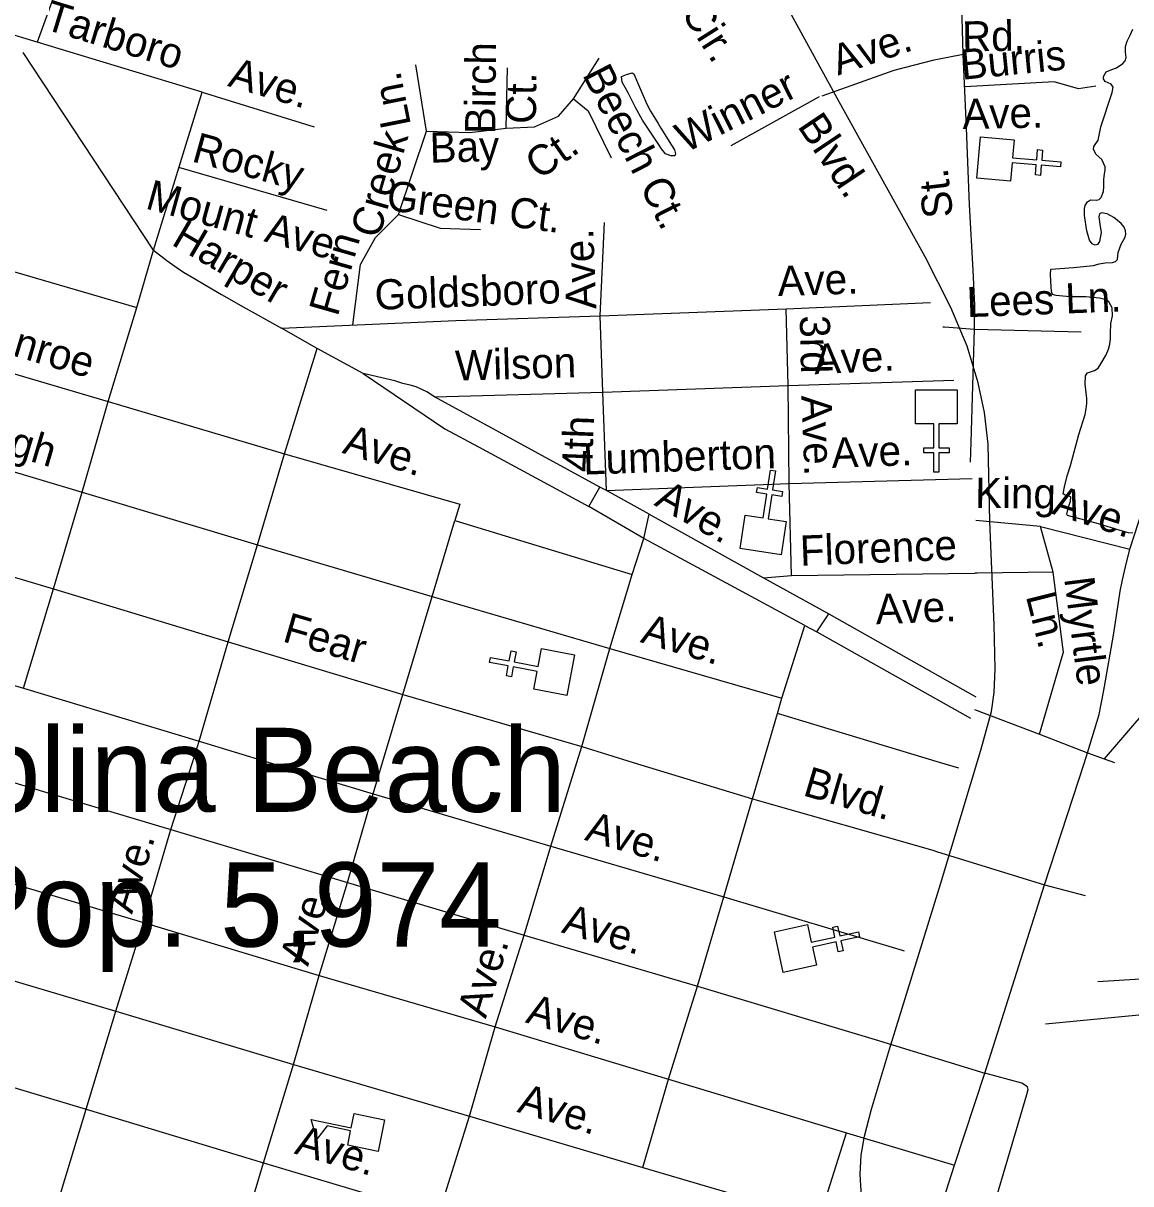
# Model space of a CAD drawing. Extents: x 2290055 to 2389491, y 66597 to 237875.
# Drawn here: x 2332155 to 2335643, y 104033 to 107689 of the extents above; entities that cross this region are included whole.
import ezdxf

# ---------------------------------------------------------------- set-up
doc = ezdxf.new("R2010")
doc.units = 0
for name, color, linetype in [('Exist Civil Demographics City Label', 7, 'Continuous'), ('Exist Cultural Church CELL', 7, 'Continuous'), ('Exist Cultural Educational Facility High CELL', 7, 'Continuous'), ('Exist Hydrographic Island Shore', 7, 'Continuous'), ('Exist Hydrographic Pond Under 1500 Sq Ft', 7, 'Continuous'), ('Exist Road Non-System Type 51', 7, 'Continuous'), ('Exist Road Non-System Type 51 Label', 7, 'Continuous'), ('Exist Road Primary US Attributed', 7, 'Continuous'), ('Exist Road Primary US Label', 7, 'Continuous')]:
    doc.layers.add(name, color=color, linetype=linetype)

msp = doc.modelspace()

# ---------------------------------------------------------------- linework, layer by layer
at = {"layer": 'Exist Cultural Church CELL'}
for points in [[(2335275.8, 107322.1), (2335271.2, 107265.4), (2335347.1, 107259.1), (2335349.7, 107291), (2335365.7, 107289.6), (2335363, 107257.7), (2335422.9, 107252.8), (2335421.6, 107236.8), (2335361.7, 107241.8), (2335359, 107209.9), (2335343.1, 107211.2), (2335345.7, 107243.1), (2335269.9, 107249.4), (2335265, 107192), (2335158.9, 107200.8), (2335169.7, 107331)], [(2335096.2, 106427.6), (2335039.3, 106427.5), (2335039.3, 106351.3), (2335071.3, 106351.3), (2335071.3, 106335.4), (2335039.3, 106335.4), (2335039.3, 106275.2), (2335023.2, 106275.2), (2335023.2, 106335.4), (2334991.2, 106335.4), (2334991.2, 106351.3), (2335023.2, 106351.3), (2335023.2, 106427.5), (2334965.6, 106427.6), (2334965.6, 106534), (2335096.2, 106534)], [(2334429, 106139.2), (2334485.3, 106130.6), (2334496.8, 106205.9), (2334465.2, 106210.8), (2334467.7, 106226.6), (2334499.3, 106221.7), (2334508.4, 106281.1), (2334524.3, 106278.7), (2334515.1, 106219.2), (2334546.7, 106214.4), (2334544.3, 106198.6), (2334512.7, 106203.5), (2334501.1, 106128.2), (2334558.1, 106119.3), (2334541.9, 106014.1), (2334412.8, 106034)], [(2333763, 105591.2), (2333773.6, 105647.1), (2333698.8, 105661.4), (2333692.8, 105629.9), (2333677.1, 105632.9), (2333683.1, 105664.4), (2333624, 105675.6), (2333627, 105691.3), (2333686.1, 105680.1), (2333692.1, 105711.5), (2333707.7, 105708.6), (2333701.8, 105677.1), (2333776.6, 105662.9), (2333787.5, 105719.5), (2333892, 105699.6), (2333867.6, 105571.3)], [(2334624.8, 104849.4), (2334637.3, 104793.8), (2334711.6, 104810.3), (2334704.7, 104841.6), (2334720.3, 104845), (2334727.2, 104813.8), (2334785.9, 104826.8), (2334789.4, 104811.2), (2334730.7, 104798.2), (2334737.6, 104766.9), (2334722, 104763.5), (2334715.1, 104794.7), (2334640.8, 104778.2), (2334653.2, 104721.9), (2334549.2, 104698.8), (2334520.9, 104826.3)]]:
    msp.add_lwpolyline(points, close=True, dxfattribs=at)
at = {"layer": 'Exist Cultural Educational Facility High CELL'}
msp.add_lwpolyline([(2333273.1, 104135), (2333177.2, 104154.9), (2333186.5, 104199.9), (2333113, 104215.1), (2333079.7, 104174), (2333062.6, 104235.4), (2333188.5, 104209.3), (2333197.8, 104254.4), (2333293.7, 104234.6)], close=True, dxfattribs=at)
at = {"layer": 'Exist Hydrographic Island Shore'}
for points in [[(2335497.5, 107083.2), (2335497.2, 107105.3), (2335499.5, 107114.9), (2335507.2, 107126.2), (2335516.2, 107132.6), (2335536.2, 107131.9), (2335543.7, 107133.9), (2335550.5, 107140), (2335558, 107158.8), (2335558.7, 107175), (2335558.5, 107196.4), (2335560.5, 107214.7), (2335563.2, 107225.9), (2335562.7, 107236.9), (2335552, 107259.7), (2335534, 107275.5), (2335526.2, 107291.5), (2335527.5, 107300.4), (2335540.5, 107320.3), (2335549.2, 107362.8), (2335585.2, 107470.6), (2335587.5, 107487.6), (2335582, 107496.7), (2335562.5, 107505.5), (2335557.7, 107514.1), (2335557.2, 107521.6), (2335565.7, 107535.8), (2335583.7, 107543.9), (2335598, 107548.8), (2335618.5, 107562.3), (2335626.2, 107571.1), (2335629.2, 107580.8), (2335627.2, 107598), (2335627, 107615.8), (2335632, 107632.8), (2335641.5, 107651.2), (2335650.2, 107670.5)], [(2335504.7, 106507.3), (2335500.2, 106552.2), (2335500.5, 106578.1), (2335507.5, 106588), (2335529, 106594.8), (2335540.7, 106602.7), (2335549, 106615.8), (2335565.5, 106645), (2335573, 106662.8), (2335577.7, 106678.2), (2335580, 106695.5), (2335579.5, 106711.9), (2335580.5, 106743.2), (2335585.7, 106767.8), (2335584.7, 106792.1), (2335574.5, 106811.4), (2335565.5, 106818.2), (2335544.5, 106823.1), (2335501.5, 106827.1), (2335453, 106827.6), (2335429, 106829.1), (2335408.5, 106831.1), (2335396.5, 106834.6), (2335393.5, 106843.6), (2335391.2, 106875.9), (2335390.5, 106899.1), (2335392, 106914.8), (2335463.2, 106919.2), (2335526, 106926), (2335544, 106931.6), (2335563.2, 106933.9), (2335586, 106935.4), (2335595.5, 106938.3), (2335601.5, 106944.9), (2335604.2, 106966.8), (2335613.5, 106993), (2335625.7, 107015.6), (2335628.2, 107024.6), (2335627, 107035.6), (2335622.2, 107046.3), (2335612.7, 107058.2), (2335590, 107076.7), (2335568.7, 107088.7), (2335550.7, 107091.4), (2335544.7, 107088.7), (2335542.7, 107079.7), (2335545.5, 107055.8), (2335549.7, 107030), (2335544.7, 107001.9), (2335538.7, 106992.5), (2335531, 106989.8), (2335521.5, 106994.3), (2335513, 107005.4), (2335504.5, 107035.5), (2335497.5, 107083.2)], [(2335650, 106082.3), (2335636.5, 106083.9), (2335610.2, 106090.9), (2335542, 106112.5), (2335443.7, 106138.1), (2335442.5, 106142.1), (2335447.5, 106164.6), (2335453.2, 106183.3), (2335454.2, 106196.8), (2335435.2, 106203.6), (2335430.5, 106206.9), (2335434.2, 106228.5), (2335443, 106263.4), (2335453.2, 106296.2), (2335479.7, 106393.8), (2335499.5, 106456.8), (2335503.2, 106474.4), (2335505.5, 106491.3), (2335504.7, 106507.3)]]:
    msp.add_lwpolyline(points, dxfattribs=at)
at = {"layer": 'Exist Hydrographic Pond Under 1500 Sq Ft'}
msp.add_lwpolyline([(2334207.2, 107271.5), (2334194.5, 107271.6), (2334178.2, 107277.9), (2334166, 107293.8), (2334155.7, 107307.9), (2334105.5, 107383.7), (2334084, 107424.2), (2334060.5, 107469.4), (2334041.2, 107504), (2334039.7, 107521), (2334055.5, 107527.9), (2334072.7, 107532.9), (2334078, 107530.1), (2334089.5, 107502.5), (2334102.5, 107473.2), (2334115.7, 107441.6), (2334123.2, 107425.7), (2334131, 107411.8), (2334146.2, 107386.9), (2334155.5, 107373.1), (2334163, 107359), (2334181, 107330.7), (2334194.7, 107308.1), (2334206, 107290.6), (2334210, 107277.5), (2334207.2, 107271.5)], dxfattribs=at)
at = {"layer": 'Exist Road Non-System Type 51'}
for p, q in [((2332718.5, 107472.4), (2332130.5, 107650.4)), ((2332565.8, 106974.7), (2332155, 107596.6)), ((2332565.8, 106974.7), (2332718.5, 107472.4)), ((2332718.5, 107472.4), (2333071.7, 107362.3)), ((2334662, 107457.6), (2334384.4, 107302.9)), ((2331961.7, 106954.5), (2332513.5, 106794.1)), ((2332513.5, 106794.1), (2332565.8, 106974.7)), ((2334558.2, 106789.1), (2335012.5, 106809.3)), ((2332422.8, 106497.1), (2332513.5, 106794.1)), ((2333972.2, 106767.3), (2334558.2, 106789.1)), ((2333980.7, 106527.4), (2333972.2, 106767.3)), ((2334564.8, 106547.5), (2334558.2, 106789.1)), ((2333081.2, 106664.2), (2332968.4, 106728.7)), ((2335051.4, 106732.7), (2335057, 106732.3)), ((2335057, 106732.3), (2335150.8, 106725.2)), ((2335140.8, 106369), (2335150.8, 106725.2)), ((2331874.9, 106659.6), (2332422.8, 106497.1)), ((2332978.4, 106332.9), (2333081.2, 106664.2)), ((2333225.8, 106585.6), (2333081.2, 106664.2)), ((2333980.7, 106527.4), (2334564.8, 106547.5)), ((2334564.8, 106547.5), (2335086, 106564.3)), ((2334568.1, 106239.1), (2334564.8, 106547.5)), ((2333450.6, 106511.7), (2333980.7, 106527.4)), ((2333971.8, 106227.1), (2333450.6, 106511.7)), ((2333991.9, 106217.3), (2333980.7, 106527.4)), ((2332341.5, 106212.3), (2332422.8, 106497.1)), ((2332422.8, 106497.1), (2332978.4, 106332.9)), ((2331789.9, 106376.6), (2332341.5, 106212.3)), ((2335139.1, 106306.3), (2335140.8, 106369)), ((2332893.6, 106045.7), (2332978.4, 106332.9)), ((2334568.1, 106239.1), (2335143.6, 106255)), ((2333936.5, 106166.6), (2333971.8, 106227.1)), ((2333991.9, 106217.3), (2333971.8, 106227.1)), ((2333991.9, 106217.3), (2334568.1, 106239.1)), ((2334126.8, 106142.6), (2333991.9, 106217.3)), ((2334574.9, 105949.2), (2334568.1, 106239.1)), ((2332250.8, 105907.1), (2332341.5, 106212.3)), ((2332341.5, 106212.3), (2332893.6, 106045.7)), ((2335640.6, 106032.3), (2335696.8, 106206.8)), ((2334109.8, 106066.4), (2333936.5, 106166.6)), ((2334109.8, 106066.4), (2334126.8, 106142.6)), ((2334126.8, 106142.6), (2334486.9, 105942.1)), ((2333443.2, 105883.6), (2333514.8, 106122.4)), ((2333514.8, 106122.4), (2334073, 105952.1)), ((2335359.5, 106103.2), (2335155.2, 106123.1)), ((2331700.8, 106071.5), (2332250.8, 105907.1)), ((2335359.5, 106103.2), (2335640.6, 106032.3)), ((2335399, 105959.7), (2335359.5, 106103.2)), ((2332800.6, 105740.7), (2332893.6, 106045.7)), ((2332893.6, 106045.7), (2333443.2, 105883.6)), ((2334073, 105952.1), (2334109.8, 106066.4)), ((2334616.6, 105791.7), (2334109.8, 106066.4)), ((2335399, 105959.7), (2335159.2, 105957.1)), ((2334003, 105719.2), (2334073, 105952.1)), ((2334486.9, 105942.1), (2334574.9, 105949.2)), ((2334486.9, 105942.1), (2334692.3, 105828.5)), ((2334574.9, 105949.2), (2335152.6, 105957.1)), ((2335159.2, 105957.1), (2335152.6, 105957.1)), ((2332155.9, 105594.2), (2332250.8, 105907.1)), ((2332250.8, 105907.1), (2332800.6, 105740.7)), ((2333350.7, 105574.3), (2333443.2, 105883.6)), ((2333443.2, 105883.6), (2334003, 105719.2)), ((2334655.1, 105771.9), (2334692.3, 105828.5)), ((2334692.3, 105828.5), (2335155.2, 105567.1)), ((2334544.9, 105562.7), (2334616.6, 105791.7)), ((2334616.6, 105791.7), (2334655.1, 105771.9)), ((2331608.1, 105758.6), (2332155.9, 105594.2)), ((2332709.9, 105427.6), (2332800.6, 105740.7)), ((2332800.6, 105740.7), (2333350.7, 105574.3)), ((2334655.1, 105771.9), (2335139, 105499.7)), ((2333914.5, 105410.2), (2334003, 105719.2)), ((2334003, 105719.2), (2334544.9, 105562.7)), ((2332155.9, 105594.2), (2332709.9, 105427.6)), ((2333287.2, 105360.7), (2333350.7, 105574.3)), ((2333350.7, 105574.3), (2333914.5, 105410.2)), ((2334531.3, 105514.6), (2334544.9, 105562.7)), ((2335151.5, 105526.9), (2335356.4, 105449)), ((2334486.2, 105360.7), (2334531.3, 105514.6)), ((2335040.7, 105360.7), (2334531.3, 105514.6)), ((2335356.4, 105449), (2335507.1, 105390.6)), ((2332688.5, 105360.7), (2332709.9, 105427.6)), ((2332709.9, 105427.6), (2332930.4, 105360.7)), ((2333899.2, 105360.7), (2333914.5, 105410.2)), ((2333914.5, 105410.2), (2334076, 105360.7)), ((2335497.4, 105360.7), (2335507.1, 105390.6)), ((2335507.1, 105390.6), (2335559.4, 105371.3)), ((2332620.8, 105149.1), (2332688.5, 105360.7)), ((2332930.4, 105360.7), (2333257.7, 105261.5)), ((2333257.7, 105261.5), (2333287.2, 105360.7)), ((2333817.5, 105097.1), (2333899.2, 105360.7)), ((2334076, 105360.7), (2334452.3, 105245.6)), ((2334452.3, 105245.6), (2334486.2, 105360.7)), ((2335101.4, 105342.4), (2335040.7, 105360.7)), ((2335371.5, 104975), (2335497.4, 105360.7)), ((2335559.4, 105371.3), (2335591.8, 105360.7)), ((2333176.8, 104982.6), (2333257.7, 105261.5)), ((2333257.7, 105261.5), (2333817.5, 105097.1)), ((2334361.5, 104936.8), (2334452.3, 105245.6)), ((2334452.3, 105245.6), (2335020.3, 105083.6)), ((2332533.9, 104855.8), (2332620.8, 105149.1)), ((2332620.8, 105149.1), (2333176.8, 104982.6)), ((2333732.8, 104816.1), (2333817.5, 105097.1)), ((2333817.5, 105097.1), (2334361.5, 104936.8)), ((2335020.3, 105083.6), (2335031.6, 105080.3)), ((2335031.6, 105080.3), (2335371.5, 104975)), ((2333087.9, 104689.6), (2333176.8, 104982.6)), ((2333176.8, 104982.6), (2333732.8, 104816.1)), ((2335183.6, 104381), (2335371.5, 104975)), ((2335371.5, 104975), (2335499.9, 104940.7)), ((2334278.4, 104655.8), (2334361.5, 104936.8)), ((2334361.5, 104936.8), (2334923.4, 104768.6)), ((2332446.7, 104576.7), (2332533.9, 104855.8)), ((2332533.9, 104855.8), (2333087.9, 104689.6)), ((2333641.8, 104527), (2333732.8, 104816.1)), ((2333732.8, 104816.1), (2334278.4, 104655.8)), ((2334923.4, 104768.6), (2334929.4, 104766.8)), ((2333006.7, 104408.7), (2333087.9, 104689.6)), ((2333087.9, 104689.6), (2333641.8, 104527)), ((2334187.5, 104362.8), (2334278.4, 104655.8)), ((2334278.4, 104655.8), (2334838.4, 104487.6)), ((2332353.9, 104267.8), (2332446.7, 104576.7)), ((2332446.7, 104576.7), (2333006.7, 104408.7)), ((2333560.6, 104246.1), (2333641.8, 104527)), ((2333641.8, 104527), (2334187.5, 104362.8)), ((2334838.4, 104487.6), (2335183.6, 104381)), ((2332912, 104099.4), (2333006.7, 104408.7)), ((2333006.7, 104408.7), (2333560.6, 104246.1)), ((2334106.3, 104083.8), (2334187.5, 104362.8)), ((2334187.5, 104362.8), (2334748.2, 104193.5)), ((2335088.6, 104092.1), (2335183.6, 104381)), ((2332265, 103976.7), (2332353.9, 104267.8)), ((2332353.9, 104267.8), (2332912, 104099.4)), ((2333463.6, 103935.1), (2333560.6, 104246.1)), ((2333560.6, 104246.1), (2334106.3, 104083.8)), ((2334662.1, 103921.6), (2334748.2, 104193.5)), ((2334748.2, 104193.5), (2335088.6, 104092.1)), ((2332825, 103806.5), (2332912, 104099.4)), ((2332912, 104099.4), (2333463.6, 103935.1)), ((2334106.3, 104083.8), (2334662.1, 103921.6)), ((2335001.5, 103821.1), (2335088.6, 104092.1))]:
    msp.add_line(p, q, dxfattribs=at)
for points in [[(2332325.8, 108021.8), (2332300.3, 107907.3), (2332199.1, 107629.7)], [(2335116, 107591.3), (2335109.6, 107821.5)], [(2333676.1, 107358.1), (2333765.2, 107362.3), (2333841.5, 107396.3), (2333888.2, 107451.5), (2333968.8, 107578.8)], [(2334671.2, 107460.8), (2334898.4, 107541), (2335024.1, 107574.2), (2335116, 107591.3)], [(2335150.8, 106725.2), (2335152.2, 106799.4), (2335147.1, 106911.5), (2335135, 107117.1), (2335126.5, 107359.3), (2335116, 107591.3)], [(2333193.6, 106738.5), (2333218.1, 106929.4), (2333264.7, 107014.3), (2333336.8, 107086.5), (2333425.9, 107349.6), (2333392, 107557.6)], [(2333425.9, 107349.6), (2333561.6, 107345.4), (2333676.1, 107358.1), (2333680.4, 107549.1)], [(2335533.7, 107491.3), (2335478.6, 107482.9), (2335402.2, 107504.1), (2335120.6, 107489)], [(2333888.2, 107451.5), (2333934.8, 107413.3), (2334006.9, 107264.7)], [(2333112.1, 107099.2), (2332645.5, 107234.5)], [(2333336.8, 107086.5), (2333468.3, 107044), (2333595.5, 107039.8)], [(2333972.2, 106767.3), (2333985.7, 107061)], [(2332565.8, 106974.7), (2332608.2, 106941.3), (2332639.9, 106918.2), (2332660.1, 106904.9), (2332692.7, 106886.2), (2332732, 106863.4), (2332779.4, 106834.8), (2332847.6, 106795.8), (2332968.4, 106728.7)], [(2332968.4, 106728.7), (2333518.2, 106752.7), (2333972.2, 106767.3)], [(2335150.8, 106725.2), (2335487, 106717.2)], [(2333450.6, 106511.7), (2333426.6, 106527.5), (2333410.6, 106535.4), (2333392.5, 106543.2), (2333374.3, 106549.1), (2333350.4, 106554.7), (2333326.1, 106562.6), (2333225.8, 106585.6)], [(2333225.8, 106585.6), (2333483.7, 106411.9), (2333588.7, 106355), (2333936.5, 106166.6)], [(2332978.4, 106332.9), (2333530.5, 106174.5), (2333514.8, 106122.4)], [(2335979.5, 106127.7), (2335899.6, 105907), (2335827.9, 105712.1), (2335818.2, 105684.2), (2335806.1, 105665.6), (2335792.5, 105643.4), (2335693.7, 105528.6), (2335559.4, 105371.3)], [(2335507.1, 105390.6), (2335543.7, 105511.2), (2335549.5, 105539), (2335553.3, 105559.2), (2335560.9, 105599.2), (2335589.3, 105761.5), (2335604.3, 105863.8), (2335609.8, 105899.8), (2335616.9, 105935.5), (2335626.4, 105976.9), (2335640.6, 106032.3)], [(2335356.4, 105449), (2335427.8, 105694), (2335431.9, 105708), (2335429.6, 105724), (2335399, 105959.7)], [(2331916.6, 105360.7), (2332219.6, 105268.8), (2332620.8, 105149.1)], [(2331438.1, 105184.8), (2332108.4, 104983.4), (2332533.9, 104855.8)], [(2331350.9, 104899.7), (2331977.2, 104716), (2332446.7, 104576.7)], [(2331262.2, 104594.6), (2331816.2, 104428.4), (2332353.9, 104267.8)], [(2335155.8, 103770.4), (2335316.2, 104314.4), (2335320.2, 104330.3), (2335317.9, 104338.4), (2335300, 104350.2), (2335183.6, 104381)]]:
    msp.add_lwpolyline(points, dxfattribs=at)
at = {"layer": 'Exist Road Non-System Type 51 Label'}
for points in [[(2336060.9, 104701.8), (2335539.4, 104668.8)], [(2336060.9, 104602.2), (2335374.7, 104536.3)]]:
    msp.add_lwpolyline(points, dxfattribs=at)
at = {"layer": 'Exist Road Primary US Attributed'}
msp.add_lwpolyline([(2334795.8, 103992.6), (2334791.2, 104063.3), (2334794.3, 104123.3), (2334805.1, 104183.2), (2334826.6, 104267.8), (2334883.4, 104456.8), (2335044.7, 104976.4), (2335170.7, 105399), (2335204.5, 105520.5), (2335213.7, 105580.4), (2335216.8, 105655.7), (2335213.7, 105794.1), (2335199.9, 106119.9), (2335193.8, 106362.8), (2335183, 106462.7), (2335163, 106556.4), (2335127.7, 106671.7), (2335077, 106793.1), (2334995.6, 106953), (2334725.2, 107441.8), (2334479.4, 107890.6)], dxfattribs=at)

# ---------------------------------------------------------------- texts
at = {"layer": 'Exist Civil Demographics City Label'}
for s, p in [('Carolina Beach', (2331441.6, 105204.7)), ('Pop. 5,974', (2331948.2, 104780.3))]:
    msp.add_text(s, height=265, dxfattribs=at).set_placement(p)
at = {"layer": 'Exist Road Non-System Type 51 Label'}
for s, rotation, p in [('Colonial Cir.', 302.2561, (2333960.5, 108142.6)), ('Tarboro', 342.9494, (2332216.9, 107672.1)), ('Rd.', 0.841, (2335112.7, 107600.1)), ('Ave.', 18.6992, (2334721.2, 107524.1)), ('Birch ', 89.414, (2333641.7, 107339.5)), ('Burris', 5.7107, (2335112.1, 107510.8)), ('Ave.', 343.4764, (2332796.8, 107492.1)), ('Beech Ct.', 297.117, (2333915, 107527.7)), ('Ln.', 101.2821, (2333376.8, 107368.9)), ('Ct.', 89.414, (2333770.1, 107371.6)), ('Winner', 26.9131, (2334241.4, 107279.7)), ('Ave.', 1.0532, (2335114, 107355.9)), ('Creek', 74.0171, (2333275.8, 107007.8)), ('Rocky', 344.5112, (2332682.7, 107254.8)), ('Bay ', 1.433, (2333436.6, 107249.7)), ('Ct.', 34.7799, (2333779.7, 107193.7)), ('St.', 96.6193, (2335084.4, 107081)), ('Mount Ave.', 344.5112, (2332536.8, 107106.3)), ('Green Ct.', 352.4052, (2333296.2, 107101.1)), ('Harper', 329.7459, (2332618.7, 106993.2)), ('Fern', 73.9575, (2333145.3, 106762.5)), ('Ave.', 92.2519, (2333960.5, 106789.6)), ('Ave.', 1.8708, (2334532.6, 106829.4)), ('Goldsboro', 2.0826, (2333263.9, 106786)), ('Lees Ln.', 2.1591, (2335128.3, 106763)), ('Monroe', 343.4773, (2331949.6, 106693.1)), ('3rd', 271.4011, (2334600.7, 106768)), ('Wilson', 1.6924, (2333516.9, 106562.9)), ('Ave.', 2.6716, (2334647.5, 106583.3)), ('Ave.', 272.2952, (2334605.8, 106515.8)), ('Raleigh', 343.4292, (2331829.2, 106412.8)), ('4th', 87.8875, (2333946.7, 106274)), ('Ave.', 342.8902, (2333157.2, 106336.1)), ('Lumberton', 1.9544, (2333920.2, 106267)), ('Ave.', 1.9989, (2334702.4, 106288.2)), ('King', 359.4918, (2335152.9, 106162.5)), ('Ave.', 330.5498, (2334139.6, 106172.2)), ('Ave.', 342.1793, (2335391.9, 106144.7)), ('Florence', 2.2118, (2334603.3, 105980)), ('Myrtle', 277.1962, (2335433.6, 105939.9)), ('Ave.', 2.2118, (2334841.3, 105795.7)), ('Ln.', 284.1571, (2335312.5, 105884.6)), ('Fear', 343.7576, (2332968.5, 105742.6)), ('Ave.', 343.3167, (2334096.3, 105739.9)), ('Blvd.', 343.5216, (2334607.4, 105257.6)), ('Ave.', 343.6532, (2333920.6, 105116.8)), ('Ave.', 73.2122, (2332497.9, 104880.6)), ('Ave.', 73.2122, (2333052.3, 104715.8)), ('Ave.', 343.6532, (2333847.8, 104825.3)), ('Ave.', 73.2122, (2333612.1, 104551)), ('Ave.', 343.6532, (2333734.5, 104541.8)), ('Ave.', 343.1918, (2333708, 104260)), ('Ave.', 343.6532, (2333006.4, 104128.8))]:
    msp.add_text(s, height=95, rotation=rotation, dxfattribs=at).set_placement(p)
at = {"layer": 'Exist Road Primary US Label'}
msp.add_text('Blvd.', height=95, rotation=303.8203, dxfattribs=at).set_placement((2334591.6, 107365))

doc.saveas('drawing.dxf')
